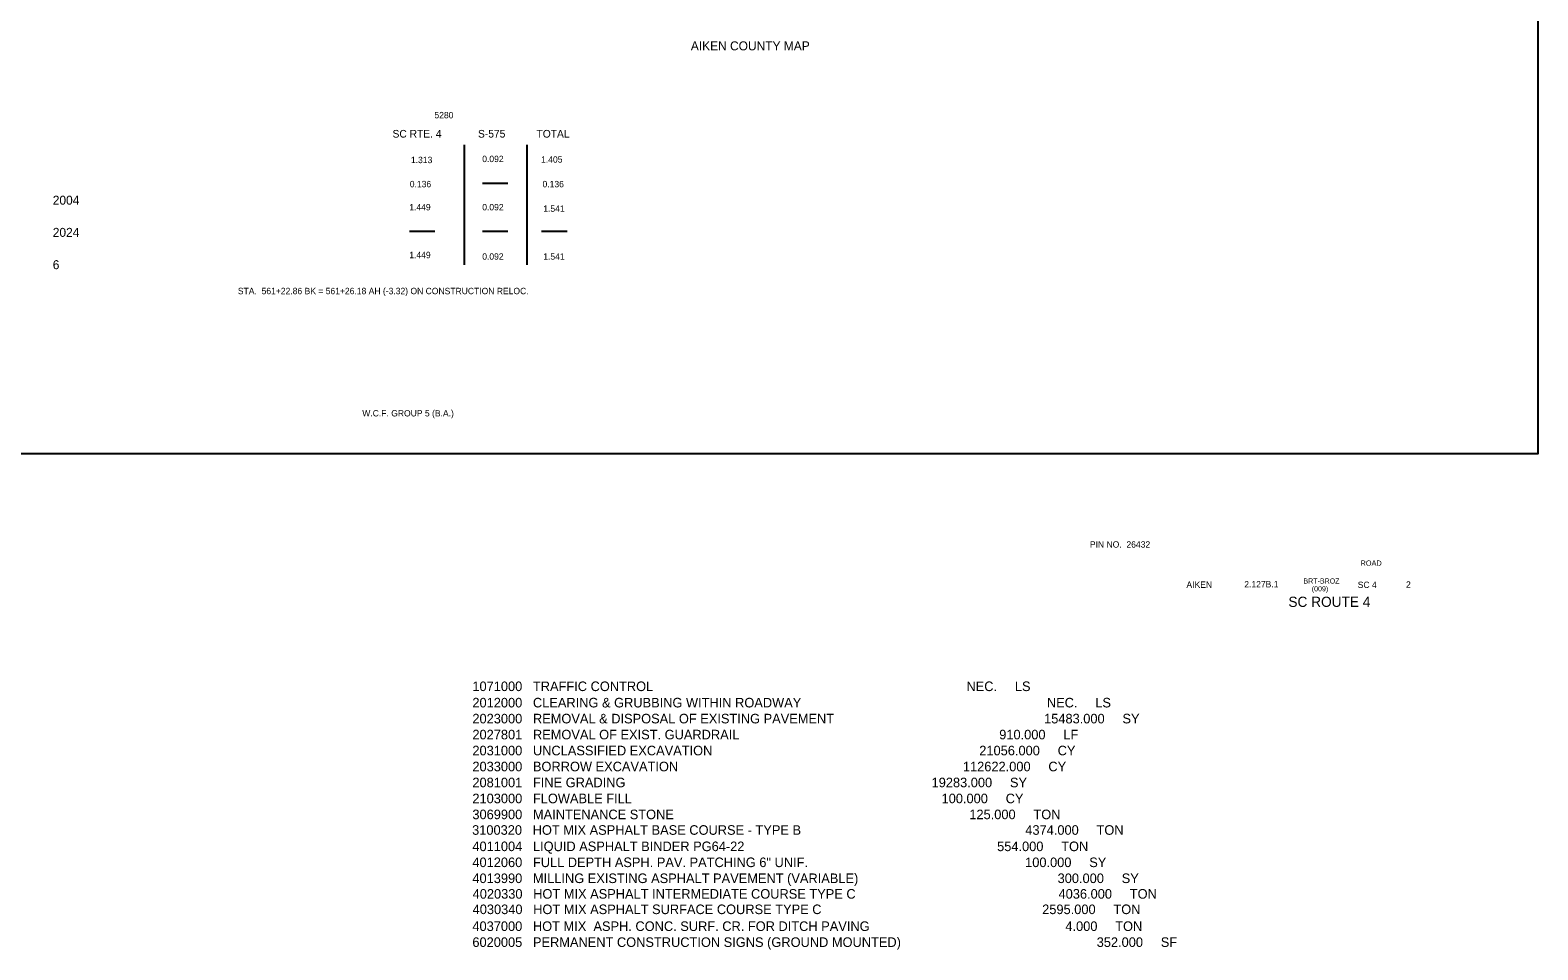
# Model space of a CAD drawing. Extents: x 17139 to 21295, y 12843 to 18076.
# Drawn here: x 17755 to 18935, y 15463 to 16183 of the extents above; entities that cross this region are included whole.
import ezdxf

# ---------------------------------------------------------------- set-up
doc = ezdxf.new("R2010")
doc.units = 0
for name, color, linetype in [('Level 1', 7, 'Continuous'), ('Level 3', 7, 'Continuous'), ('Level 50', 7, 'Continuous')]:
    doc.layers.add(name, color=color, linetype=linetype)

msp = doc.modelspace()

# ---------------------------------------------------------------- linework, layer by layer
at = {"layer": 'Level 3'}
for p, q in [((18094.3, 16093.3), (18094.3, 15999.3)), ((18143.4, 16093.3), (18143.4, 15999.3)), ((18108.5, 16063.2), (18128.5, 16063.2)), ((18051.4, 16025.7), (18071.4, 16025.7)), ((18108.5, 16025.7), (18128.5, 16025.7)), ((18154.9, 16025.7), (18175, 16025.7))]:
    msp.add_line(p, q, dxfattribs=at)
at = {"layer": 'Level 50'}
msp.add_lwpolyline([(17138.8, 16951.5), (18934.8, 16951.5), (18934.8, 15851.5), (17138.8, 15851.5)], close=True, dxfattribs=at)

# ---------------------------------------------------------------- texts
at = {"layer": 'Level 1'}
for s, height, p in [('2004', 7, (17772.2, 16046.5)), ('2024', 7, (17772.2, 16021.3)), ('6', 7, (17772.2, 15996)), ('ROAD', 4.15, (18796, 15763.8)), ('1071000   TRAFFIC CONTROL                                                                                        NEC.     LS', 7.5, (18100.7, 15665.7)), ('2012000   CLEARING & GRUBBING WITHIN ROADWAY                                                                     NEC.     LS', 7.5, (18100.7, 15652.9)), ('2023000   REMOVAL & DISPOSAL OF EXISTING PAVEMENT                                                           15483.000     SY', 7.5, (18100.7, 15640.4)), ('2027801   REMOVAL OF EXIST. GUARDRAIL                                                                         910.000     LF', 7.5, (18100.7, 15627.9)), ('2031000   UNCLASSIFIED EXCAVATION                                                                           21056.000     CY', 7.5, (18100.7, 15615.4)), ('2033000   BORROW EXCAVATION                                                                                112622.000     CY', 7.5, (18100.7, 15602.9)), ('2081001   FINE GRADING                                                                                      19283.000     SY', 7.5, (18100.7, 15590.4)), ('2103000   FLOWABLE FILL                                                                                       100.000     CY', 7.5, (18100.7, 15577.9)), ('3069900   MAINTENANCE STONE                                                                                   125.000     TON', 7.5, (18100.7, 15565.4)), ('3100320   HOT MIX ASPHALT BASE COURSE - TYPE B                                                               4374.000     TON', 7.5, (18100.5, 15553.2)), ('4011004   LIQUID ASPHALT BINDER PG64-22                                                                       554.000     TON', 7.5, (18100.7, 15540.4)), ('4012060   FULL DEPTH ASPH. PAV. PATCHING 6" UNIF.                                                             100.000     SY', 7.5, (18100.7, 15527.9)), ('4013990   MILLING EXISTING ASPHALT PAVEMENT (VARIABLE)                                                        300.000     SY', 7.5, (18100.7, 15515.4)), ('4020330   HOT MIX ASPHALT INTERMEDIATE COURSE TYPE C                                                         4036.000     TON', 7.5, (18100.9, 15503.2)), ('4030340   HOT MIX ASPHALT SURFACE COURSE TYPE C                                                              2595.000     TON', 7.5, (18100.9, 15491.1)), ('4037000   HOT MIX  ASPH. CONC. SURF. CR. FOR DITCH PAVING                                                       4.000     TON', 7.5, (18100.7, 15477.9)), ('6020005   PERMANENT CONSTRUCTION SIGNS (GROUND MOUNTED)                                                       352.000     SF', 7.5, (18100.7, 15465.4))]:
    msp.add_text(s, height=height, dxfattribs=at).set_placement(p)
at = {"layer": 'Level 3'}
for s, height, p in [('AIKEN COUNTY MAP', 7, (18271.7, 16167.3)), ('5280', 5, (18071, 16114.1)), ('SC RTE. 4', 6, (18038.2, 16099)), ('S-575', 6, (18105.1, 16099)), ('TOTAL', 6, (18150.9, 16099)), ('1.313', 5, (18052.6, 16079)), ('0.092', 5, (18108.4, 16079.8)), ('1.405', 5, (18154.5, 16079.4)), ('0.136', 5, (18051.7, 16060.1)), ('0.136', 5, (18155.6, 16060.1)), ('1.449', 5, (18051.3, 16042)), ('0.092', 5, (18108.4, 16042)), ('1.541', 5, (18156.2, 16040.9)), ('1.449', 5, (18051.3, 16004.6)), ('0.092', 5, (18108.4, 16003.4)), ('1.541', 5, (18156.2, 16003.4)), ('STA.  561+22.86 BK = 561+26.18 AH (-3.32) ON CONSTRUCTION RELOC.', 5, (17917.1, 15976.4)), ('W.C.F. GROUP 5 (B.A.)', 5, (18014.5, 15880.7)), ('PIN NO.  26432', 5, (18584.1, 15778)), ('AIKEN', 5, (18659.7, 15746.5)), (' 2.127B.1', 5, (18703.1, 15746.8)), ('BRT-BROZ', 4, (18751.3, 15749.9)), ('(009)', 4, (18757.8, 15743.8)), ('SC 4', 5, (18793.8, 15746.4)), ('2', 5, (18831.6, 15746.6)), ('SC ROUTE 4', 8, (18739.5, 15731.6))]:
    msp.add_text(s, height=height, dxfattribs=at).set_placement(p)

doc.saveas('drawing.dxf')
